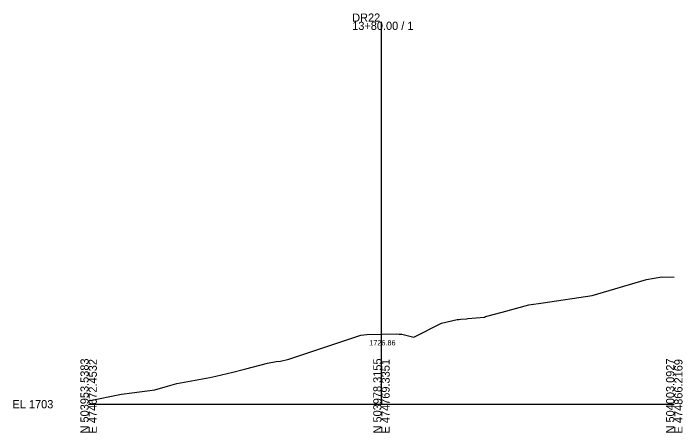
# Model space of a CAD drawing. Extents: x -26 to 1203, y -10 to 9633.
# Drawn here: x -25.7 to 202.8, y 9490.3 to 9633.4 of the extents above; entities that cross this region are included whole.
import ezdxf

# ---------------------------------------------------------------- set-up
doc = ezdxf.new("R2010")
doc.units = 0
for name, color, linetype in [('Exist Cross Section Cell', 7, 'Continuous'), ('Exist XS Center Line Elevation Label', 7, 'Continuous'), ('Exist XS Ground Line', 7, 'Continuous'), ('Scratch_Level_5', 7, 'Continuous')]:
    doc.layers.add(name, color=color, linetype=linetype)

msp = doc.modelspace()

# ---------------------------------------------------------------- linework, layer by layer
at = {"layer": 'Exist Cross Section Cell'}
for p, q in [((100, 9500), (100, 9630.52)), ((0, 9500), (100, 9500)), ((100, 9500), (200, 9500))]:
    msp.add_line(p, q, dxfattribs=at)
at = {"layer": 'Exist XS Ground Line'}
msp.add_lwpolyline([(0, 9501.1), (11.27, 9503.38), (14.77, 9503.87), (22.65, 9504.95), (26.88, 9506.1), (30.1, 9507.02), (41.38, 9509.12), (43.4, 9509.52), (49.26, 9510.91), (52.81, 9511.81), (53.72, 9512.03), (61.03, 9513.96), (64.04, 9514.57), (65.53, 9514.67), (68.39, 9515.4), (93, 9523.6), (93.98, 9523.68), (95, 9523.76), (100, 9523.86), (105, 9523.96), (106.02, 9523.92), (107, 9523.88), (111, 9522.88), (120.53, 9527.64), (125.82, 9528.89), (126.42, 9528.94), (127.11, 9529), (129.07, 9529.18), (129.45, 9529.21), (135.2, 9529.71), (135.57, 9529.97), (141.18, 9531.38), (150.38, 9533.94), (155.23, 9534.62), (171.98, 9537.15), (190.53, 9542.61), (195.78, 9543.51), (200, 9543.35)], dxfattribs=at)
at = {"layer": 'Scratch_Level_5'}
msp.add_lwpolyline([(0, 9501.1), (11.27, 9503.38), (14.77, 9503.87), (22.65, 9504.95), (26.88, 9506.1), (30.1, 9507.02), (41.38, 9509.12), (43.4, 9509.52), (49.26, 9510.91), (52.81, 9511.81), (53.72, 9512.03), (61.03, 9513.96), (64.04, 9514.57), (65.53, 9514.67), (68.39, 9515.4), (93, 9523.6), (93.98, 9523.68), (95, 9523.76), (100, 9523.86), (105, 9523.96), (106.02, 9523.92), (107, 9523.88), (111, 9522.88), (120.53, 9527.64), (125.82, 9528.89), (126.42, 9528.94), (127.11, 9529), (129.07, 9529.18), (129.45, 9529.21), (135.2, 9529.71), (135.57, 9529.97), (141.18, 9531.38), (150.38, 9533.94), (155.23, 9534.62), (171.98, 9537.15), (190.53, 9542.61), (195.78, 9543.51), (200, 9543.35)], dxfattribs=at)

# ---------------------------------------------------------------- texts
at = {"layer": 'Exist Cross Section Cell'}
for s, p in [('DR22', (90, 9630.52)), ('13+80.00 / 1', (90, 9627.72)), ('EL 1703', (-26, 9498.6))]:
    msp.add_text(s, height=2.8, dxfattribs=at).set_placement(p)
for s, p in [('N 503953.5383', (0, 9490)), ('E 474672.4532', (2.8, 9490)), ('N 503978.3155', (100, 9490)), ('E 474769.3351', (102.8, 9490)), ('N 504003.0927', (200, 9490)), ('E 474866.2169', (202.8, 9490))]:
    msp.add_text(s, height=2.8, rotation=90, dxfattribs=at).set_placement(p)
at = {"layer": 'Exist XS Center Line Elevation Label'}
msp.add_text('1726.86', height=1.8, dxfattribs=at).set_placement((95.83, 9520.06))

doc.saveas('drawing.dxf')
